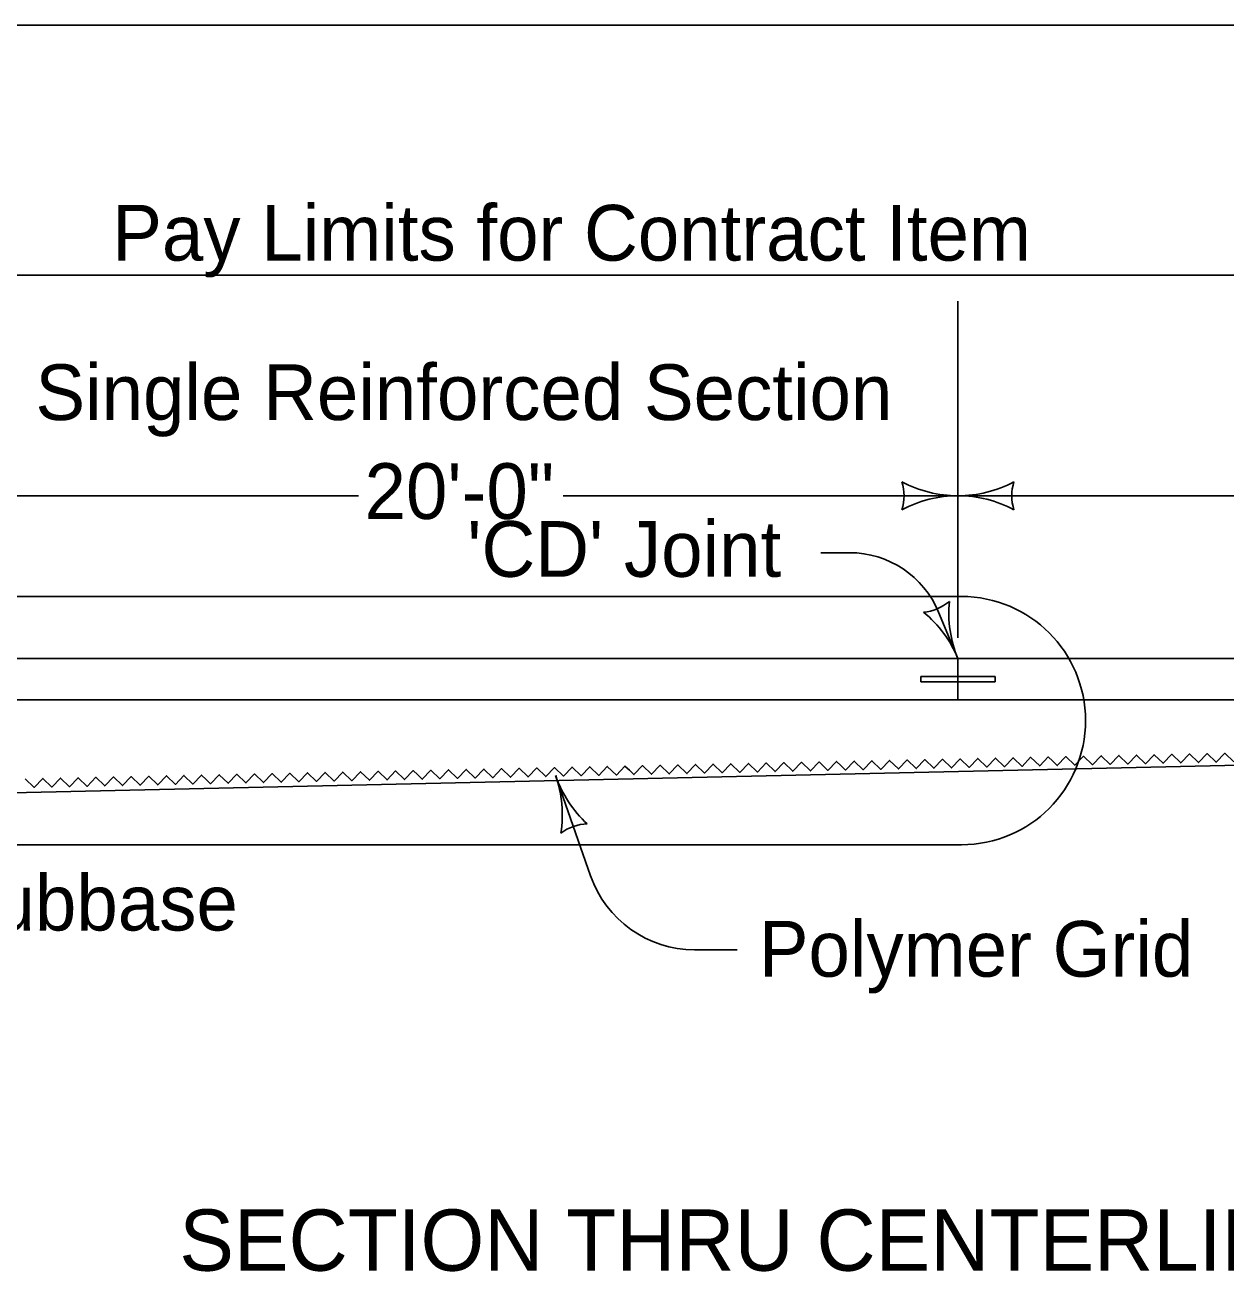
# Model space of a CAD drawing. Extents: x -2135039 to -2120895, y -2139150 to -2136566.
# Drawn here: x -2126862.4 to -2126431.3, y -2137490.2 to -2137035.9 of the extents above; entities that cross this region are included whole.
import ezdxf

# ---------------------------------------------------------------- set-up
doc = ezdxf.new("R2010")
doc.units = 0
for name, color, linetype in [('dsnStdDimension', 7, 'Continuous'), ('dsnStdLabel', 7, 'Continuous'), ('dsnStdLineWork', 7, 'Continuous'), ('Level 1', 7, 'Continuous'), ('Level 2', 7, 'Continuous'), ('Level 3', 7, 'Continuous')]:
    doc.layers.add(name, color=color, linetype=linetype)

msp = doc.modelspace()

# ---------------------------------------------------------------- linework, layer by layer
at = {"layer": 'dsnStdDimension'}
for p, q in [((-2127329.35, -2137125.64), (-2125992.85, -2137125.64)), ((-2126527.45, -2137255.84), (-2126527.45, -2137134.99)), ((-2126883.85, -2137204.84), (-2126742.69, -2137204.84)), ((-2126669.17, -2137204.84), (-2126527.45, -2137204.84)), ((-2126527.45, -2137204.84), (-2126386.67, -2137204.84))]:
    msp.add_line(p, q, dxfattribs=at)
for centre, radius, start, end in [((-2126563.3, -2137204.84), 16.51, 342.2666, 17.7333), ((-2126527.45, -2137162.09), 42.75, 241.9275, 270), ((-2126563.3, -2137204.84), 16.51, 342.2666, 17.7333), ((-2126527.45, -2137162.09), 42.75, 241.9275, 270), ((-2126527.45, -2137162.09), 42.75, 270, 298.0725), ((-2126527.45, -2137162.09), 42.75, 270, 298.0725), ((-2126491.61, -2137204.84), 16.51, 162.2666, 197.7334), ((-2126491.61, -2137204.84), 16.51, 162.2666, 197.7334), ((-2126527.45, -2137247.58), 42.75, 90, 118.0725), ((-2126527.45, -2137247.58), 42.75, 90, 118.0725), ((-2126527.45, -2137247.58), 42.75, 61.9275, 90), ((-2126527.45, -2137247.58), 42.75, 61.9275, 90)]:
    msp.add_arc(centre, radius, start, end, dxfattribs=at)
at = {"layer": 'dsnStdLabel'}
for p, q in [((-2126576.72, -2137225.26), (-2126566.38, -2137225.26)), ((-2127329.35, -2137240.99), (-2126526.19, -2137240.99)), ((-2126534.39, -2137246.61), (-2126527.45, -2137263.26)), ((-2126659.42, -2137341.23), (-2126671.92, -2137305.29)), ((-2127329.35, -2137330.09), (-2126526.19, -2137330.09)), ((-2126606.69, -2137367.82), (-2126622.02, -2137367.82))]:
    msp.add_line(p, q, dxfattribs=at)
for centre, radius, start, end in [((-2126566.38, -2137259.92), 34.65, 22.5907, 90), ((-2126541.22, -2137230.17), 16.51, 274.8585, 310.3252), ((-2126541.22, -2137230.17), 16.51, 274.8585, 310.3252), ((-2126487.99, -2137246.84), 42.75, 174.5193, 202.5918), ((-2126487.99, -2137246.84), 42.75, 174.5193, 202.5918), ((-2126526.19, -2137285.54), 44.55, 270.0011, 90), ((-2126566.92, -2137279.69), 42.75, 22.5918, 50.6643), ((-2126566.92, -2137279.69), 42.75, 22.5918, 50.6643), ((-2126631.54, -2137291.25), 42.75, 199.1751, 227.2476), ((-2126712.29, -2137319.33), 42.75, 351.1026, 19.1751), ((-2126631.54, -2137291.25), 42.75, 199.1751, 227.2476), ((-2126712.29, -2137319.33), 42.75, 351.1026, 19.1751), ((-2126660.14, -2137339.14), 16.51, 91.4417, 126.9084), ((-2126660.14, -2137339.14), 16.51, 91.4417, 126.9084), ((-2126622.01, -2137328.22), 39.6, 199.1769, 270)]:
    msp.add_arc(centre, radius, start, end, dxfattribs=at)
at = {"layer": 'dsnStdLineWork'}
for points in [[(-2126493.39, -2137300.14), (-2126491.77, -2137301.69), (-2126488.67, -2137298.46), (-2126485.43, -2137301.56), (-2126482.33, -2137298.32), (-2126479.1, -2137301.42), (-2126476, -2137298.19), (-2126472.77, -2137301.29), (-2126469.66, -2137298.05), (-2126466.43, -2137301.15), (-2126463.33, -2137297.91), (-2126460.09, -2137301.02), (-2126457, -2137297.78), (-2126453.76, -2137300.88), (-2126450.66, -2137297.65), (-2126447.43, -2137300.75), (-2126444.33, -2137297.51), (-2126441.09, -2137300.61), (-2126437.99, -2137297.38), (-2126434.76, -2137300.47), (-2126431.66, -2137297.24), (-2126428.42, -2137300.34)], [(-2126721.43, -2137305.02), (-2126719.81, -2137306.57), (-2126716.71, -2137303.34), (-2126713.48, -2137306.44), (-2126710.38, -2137303.2), (-2126707.14, -2137306.3), (-2126704.05, -2137303.07), (-2126700.81, -2137306.17), (-2126697.71, -2137302.93), (-2126694.47, -2137306.03), (-2126691.37, -2137302.79), (-2126688.14, -2137305.89), (-2126685.04, -2137302.66), (-2126681.81, -2137305.76), (-2126678.71, -2137302.52), (-2126675.47, -2137305.62), (-2126672.37, -2137302.39), (-2126669.13, -2137305.49), (-2126666.04, -2137302.26), (-2126662.8, -2137305.35), (-2126659.7, -2137302.12), (-2126656.47, -2137305.22), (-2126653.37, -2137301.98), (-2126650.13, -2137305.08), (-2126647.03, -2137301.85), (-2126645.41, -2137303.39)], [(-2126645.41, -2137303.39), (-2126643.8, -2137304.95), (-2126640.7, -2137301.71), (-2126637.46, -2137304.81), (-2126634.37, -2137301.57), (-2126631.13, -2137304.67), (-2126628.03, -2137301.44), (-2126624.79, -2137304.54), (-2126621.69, -2137301.3), (-2126618.46, -2137304.4), (-2126615.36, -2137301.17), (-2126612.13, -2137304.27), (-2126609.03, -2137301.04), (-2126605.79, -2137304.13), (-2126602.69, -2137300.9), (-2126599.45, -2137304), (-2126596.36, -2137300.76), (-2126593.12, -2137303.86), (-2126590.02, -2137300.63), (-2126586.79, -2137303.73), (-2126583.69, -2137300.49), (-2126580.45, -2137303.59), (-2126577.35, -2137300.35), (-2126574.12, -2137303.45), (-2126571.02, -2137300.22), (-2126569.4, -2137301.77)], [(-2126569.4, -2137301.77), (-2126567.78, -2137303.32), (-2126564.69, -2137300.09), (-2126561.45, -2137303.19), (-2126558.35, -2137299.95), (-2126555.11, -2137303.05), (-2126552.01, -2137299.82), (-2126548.78, -2137302.91), (-2126545.68, -2137299.68), (-2126542.45, -2137302.78), (-2126539.35, -2137299.54), (-2126536.11, -2137302.64), (-2126533.01, -2137299.41), (-2126529.77, -2137302.51), (-2126526.68, -2137299.27), (-2126523.44, -2137302.37), (-2126520.34, -2137299.13), (-2126517.11, -2137302.24), (-2126514.01, -2137299), (-2126510.77, -2137302.1), (-2126507.67, -2137298.87), (-2126504.44, -2137301.97), (-2126501.34, -2137298.73), (-2126498.1, -2137301.83), (-2126495.01, -2137298.6), (-2126493.39, -2137300.14)], [(-2126862.41, -2137306.45), (-2126859.17, -2137309.55), (-2126856.07, -2137306.32), (-2126852.84, -2137309.42), (-2126849.74, -2137306.18), (-2126846.5, -2137309.28), (-2126843.41, -2137306.05), (-2126840.17, -2137309.15), (-2126837.07, -2137305.91), (-2126833.83, -2137309.01), (-2126830.73, -2137305.78), (-2126827.5, -2137308.88), (-2126824.4, -2137305.64), (-2126821.17, -2137308.74), (-2126818.06, -2137305.51), (-2126814.83, -2137308.61), (-2126811.73, -2137305.37), (-2126808.49, -2137308.47), (-2126805.4, -2137305.23), (-2126802.16, -2137308.33), (-2126799.06, -2137305.1), (-2126797.45, -2137306.65)], [(-2126797.45, -2137306.65), (-2126795.83, -2137308.2), (-2126792.73, -2137304.96), (-2126789.49, -2137308.06), (-2126786.39, -2137304.83), (-2126783.16, -2137307.93), (-2126780.06, -2137304.69), (-2126776.82, -2137307.79), (-2126773.72, -2137304.56), (-2126770.49, -2137307.66), (-2126767.39, -2137304.42), (-2126764.15, -2137307.52), (-2126761.05, -2137304.29), (-2126757.82, -2137307.39), (-2126754.72, -2137304.15), (-2126751.49, -2137307.25), (-2126748.39, -2137304.01), (-2126745.15, -2137307.11), (-2126742.05, -2137303.88), (-2126738.82, -2137306.98), (-2126735.72, -2137303.74), (-2126732.48, -2137306.84), (-2126729.38, -2137303.61), (-2126726.15, -2137306.71), (-2126723.05, -2137303.47), (-2126721.43, -2137305.02)]]:
    msp.add_lwpolyline(points, dxfattribs=at)
at = {"layer": 'Level 1'}
msp.add_lwpolyline([(-2127734.46, -2137035.95), (-2124599.46, -2137035.95), (-2124599.46, -2139045.94), (-2127734.46, -2139045.94)], close=True, dxfattribs=at)
at = {"layer": 'Level 2'}
for p, q in [((-2127329.35, -2137263.26), (-2126174.44, -2137263.26)), ((-2126174.44, -2137263.26), (-2126527.46, -2137263.26)), ((-2126527.46, -2137263.27), (-2126527.46, -2137269.76)), ((-2126527.45, -2137263.26), (-2126527.45, -2137278.11)), ((-2126540.82, -2137269.76), (-2126514.09, -2137269.76)), ((-2126540.82, -2137269.76), (-2126540.82, -2137271.62)), ((-2126527.46, -2137269.76), (-2126514.1, -2137269.76)), ((-2126514.1, -2137269.76), (-2126514.1, -2137271.62)), ((-2126514.09, -2137269.76), (-2126514.09, -2137271.62)), ((-2126540.82, -2137271.62), (-2126514.09, -2137271.62)), ((-2126514.1, -2137271.62), (-2126527.46, -2137271.62)), ((-2126527.46, -2137271.62), (-2126527.46, -2137278.11)), ((-2126188.13, -2137278.11), (-2127329.35, -2137278.11)), ((-2126527.46, -2137278.11), (-2126188.14, -2137278.11)), ((-2126178.48, -2137295.93), (-2127295.72, -2137321.18))]:
    msp.add_line(p, q, dxfattribs=at)
msp.add_lwpolyline([(-2126527.46, -2137263.26), (-2126527.46, -2137263.27)], dxfattribs=at)
at = {"layer": 'Level 3'}
for p, q in [((-2126883.86, -2137263.26), (-2126527.46, -2137263.26)), ((-2126527.46, -2137263.26), (-2126527.46, -2137269.76)), ((-2126527.46, -2137269.76), (-2126540.82, -2137269.76)), ((-2126540.82, -2137269.76), (-2126540.82, -2137271.62)), ((-2126540.82, -2137271.62), (-2126527.45, -2137271.62)), ((-2126527.45, -2137271.62), (-2126527.46, -2137278.11)), ((-2126527.46, -2137278.11), (-2126883.86, -2137278.11))]:
    msp.add_line(p, q, dxfattribs=at)

# ---------------------------------------------------------------- texts
at = {"layer": 'dsnStdDimension'}
for s, p in [('Pay Limits for Contract Item', (-2126831.16, -2137120.43)), ('Single Reinforced Section', (-2126858.75, -2137177.65)), ('20\'-0"', (-2126740.56, -2137213.16))]:
    msp.add_text(s, height=20, dxfattribs=at).set_placement(p)
at = {"layer": 'dsnStdLabel'}
for s, p in [("'CD' Joint", (-2126703.67, -2137233.93)), ('Modified Subbase', (-2127000.15, -2137360.9)), ('Polymer Grid', (-2126598.97, -2137377.47))]:
    msp.add_text(s, height=20, dxfattribs=at).set_placement(p)
at = {"layer": 'Level 3'}
msp.add_text('SECTION THRU CENTERLINE', height=22, dxfattribs=at).set_placement((-2126807.08, -2137483.03))

doc.saveas('drawing.dxf')
